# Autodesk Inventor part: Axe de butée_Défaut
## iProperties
Shininess: 64.0
Length Units: 11269
Angle Units: 11279
Time Units: 11290
Mass Units: 11283
Length Display Precision: 3
Angle Display Precision: 2
Compacted: True
Part Number: Axe de butée_Défaut
Document SubType Name: Modeling
Created: 2006-11
Material: Par défaut
Designer: profs_sti
Density: 0.0
Volumn: 0.0
Area: 0.0
PropertySet Name: Model Information
Control State: 0
Master: False
Checked Out: False
Author: profs_sti
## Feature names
1. Base1
